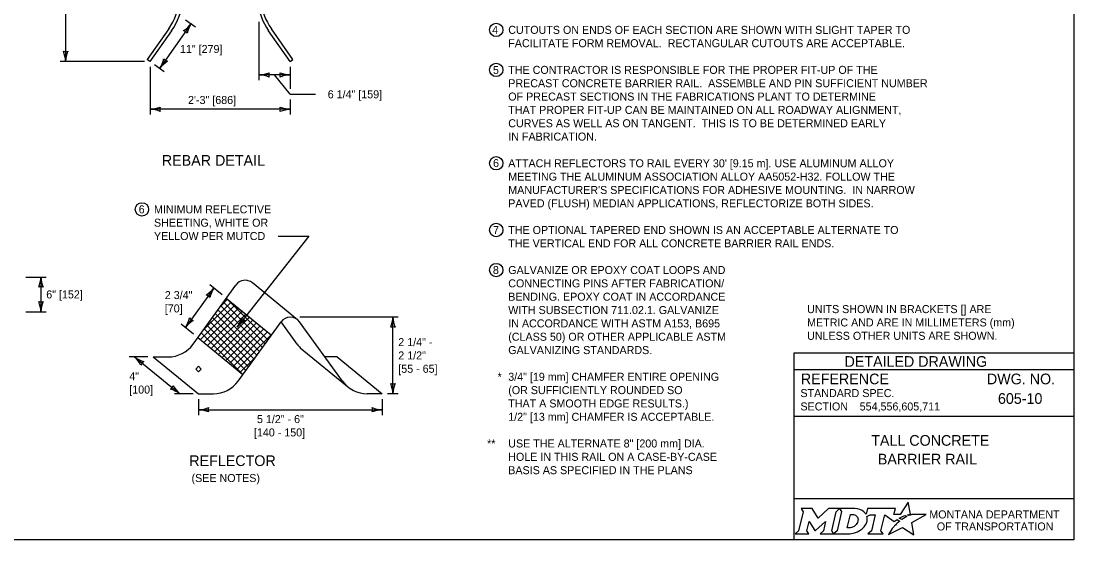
# Model space of a CAD drawing. Extents: x 49991.4 to 50021, y 49987.6 to 50011.4.
# Drawn here: x 50008.86 to 50016.75, y 49987.8 to 49991.69 of the extents above; entities that cross this region are included whole.
import ezdxf

# ---------------------------------------------------------------- set-up
doc = ezdxf.new("R2010")
doc.units = 0
for name, color, linetype in [('Default', 7, 'Continuous'), ('Level 1', 7, 'Continuous'), ('Level 2', 7, 'Continuous'), ('Level 3', 7, 'Continuous'), ('Level 5', 7, 'Continuous')]:
    doc.layers.add(name, color=color, linetype=linetype)

msp = doc.modelspace()

# ---------------------------------------------------------------- linework, layer by layer
at = {"layer": 'Default'}
for points in [[(50015.5126, 49987.9811), (50015.5023, 49987.9867), (50015.5139, 49987.9895), (50015.5255, 49987.9915), (50015.5081, 49988.0816), (50015.4486, 49987.9903), (50015.4013, 49987.9896), (50015.4116, 49988.0337), (50015.2024, 49988.0338), (50015.1923, 49987.9913), (50015.1865, 49987.9996)], [(50014.7056, 49988.0338), (50014.7197, 49988.0104), (50014.6862, 49987.8671), (50014.6605, 49987.8446), (50014.7621, 49987.8446), (50014.7486, 49987.8674), (50014.7648, 49987.9375), (50014.8085, 49987.8685), (50014.8138, 49987.8685), (50014.8889, 49987.938), (50014.8725, 49987.8669), (50014.8478, 49987.8449), (50014.9494, 49987.8449), (50014.9356, 49987.8682), (50014.9688, 49988.0106)], [(50014.9688, 49988.0106), (50014.9941, 49988.0338), (50014.9117, 49988.0338), (50014.8321, 49987.9608), (50014.7876, 49988.0335), (50014.7056, 49988.0338)], [(50015.1077, 49988.0338), (50014.9941, 49988.0338), (50015.0088, 49988.0109), (50014.9749, 49987.8671), (50014.9494, 49987.8449), (50015.06, 49987.8449)], [(50015.1317, 49987.9471), (50015.1305, 49987.939), (50015.1273, 49987.9297), (50015.1231, 49987.9215), (50015.1175, 49987.914), (50015.111, 49987.9071), (50015.1031, 49987.9008), (50015.0948, 49987.8961), (50015.0857, 49987.8922), (50015.0766, 49987.8899), (50015.0674, 49987.889), (50015.0515, 49987.889), (50015.0751, 49987.989), (50015.0911, 49987.989), (50015.0987, 49987.9884), (50015.1063, 49987.9865), (50015.1129, 49987.9835), (50015.119, 49987.9793), (50015.1238, 49987.9743), (50015.1275, 49987.9683), (50015.1302, 49987.9621), (50015.1318, 49987.9547), (50015.1318, 49987.9517), (50015.1317, 49987.9471)], [(50015.1991, 49987.9747), (50015.2237, 49987.9878), (50015.2606, 49987.9878), (50015.232, 49987.8673), (50015.2045, 49987.8446), (50015.3207, 49987.8446), (50015.3037, 49987.8675), (50015.3319, 49987.9877), (50015.4032, 49987.936), (50015.4243, 49987.9511), (50015.444, 49987.9402)], [(50015.3882, 49987.8843), (50015.3729, 49987.8599), (50015.3682, 49987.8524), (50015.3624, 49987.8438), (50015.3601, 49987.8395), (50015.4654, 49987.8926), (50015.5493, 49987.8375), (50015.5362, 49987.9302), (50015.6431, 49987.9886), (50015.5938, 49987.9894), (50015.5637, 49987.9898), (50015.5429, 49987.9901), (50015.5361, 49987.9886), (50015.5312, 49987.9874), (50015.5228, 49987.9851), (50015.5126, 49987.9811)], [(50015.4622, 49987.9535), (50015.4598, 49987.9518), (50015.4415, 49987.9614), (50015.4518, 49987.9671), (50015.4559, 49987.9693), (50015.4645, 49987.9733), (50015.4702, 49987.9759), (50015.4781, 49987.9789), (50015.4854, 49987.9816), (50015.4972, 49987.9742), (50015.4932, 49987.9721), (50015.4886, 49987.9696), (50015.4844, 49987.9674), (50015.4794, 49987.9645), (50015.4775, 49987.9634), (50015.4748, 49987.9618), (50015.4723, 49987.9604), (50015.47, 49987.9588), (50015.4674, 49987.957), (50015.4647, 49987.9552), (50015.4622, 49987.9535)], [(50015.1057, 49987.8522), (50015.1141, 49987.8548), (50015.1271, 49987.8602), (50015.1475, 49987.8712)], [(50015.4021, 49987.9004), (50015.4021, 49987.9004)]]:
    msp.add_lwpolyline(points, dxfattribs=at)
for centre, radius, start, end in [((50015.0868, 49987.9727), 0.1183, 300.91025, 339.13831), ((50015.1308, 49987.9554), 0.0709, 339.53292, 15.85821)]:
    msp.add_arc(centre, radius, start, end, dxfattribs=at)
for centre, major_axis, ratio, start_param, end_param in [((50015.1056, 49987.9864), (0.0834, -0.0037), 0.568097, 0.61298, 1.570796), ((50015.1612, 49987.9937), (0.0361, -0.0295), 0.469099, 1.225588, 1.570796), ((50015.4119, 49987.9106), (-0.0098, -0.0102), 0.016458, 3.141593, 6.279097), ((50015.4329, 49987.9305), (-0.0112, -0.0097), 0.021651, 3.157348, 6.283185), ((50015.0603, 49987.9932), (0, 0.1484), 0.987302, 3.139398, 3.456847), ((50015.3952, 49987.8923), (-0.00694, -0.00806), 0.008222, 0, 3.137361)]:
    msp.add_ellipse(centre, major_axis=major_axis, ratio=ratio, start_param=start_param, end_param=end_param, dxfattribs=at)
at = {"layer": 'Level 1'}
for p, q in [((50009.9662, 49991.6291), (50009.805, 49991.3994)), ((50010.897, 49991.3994), (50010.7358, 49991.6291)), ((50009.9869, 49991.6146), (50009.8257, 49991.385)), ((50010.8763, 49991.385), (50010.7151, 49991.6146)), ((50009.8257, 49991.385), (50009.805, 49991.3994)), ((50010.8763, 49991.385), (50010.897, 49991.3994)), ((50010.1483, 49989.2658), (50010.4691, 49989.7092)), ((50010.9322, 49989.449), (50010.5936, 49989.7253)), ((50010.2237, 49989.37), (50010.4343, 49989.5807)), ((50010.3531, 49989.549), (50010.4071, 49989.6029)), ((50010.3764, 49989.5811), (50010.6888, 49989.2686)), ((50010.3972, 49989.6098), (50010.7096, 49989.2974)), ((50010.3977, 49989.6106), (50010.7364, 49989.3343)), ((50010.2029, 49989.2997), (50010.4616, 49989.5585)), ((50010.2301, 49989.2775), (50010.4889, 49989.5362)), ((50010.2574, 49989.2553), (50010.5161, 49989.514)), ((50010.3348, 49989.5237), (50010.6473, 49989.2112)), ((50010.3556, 49989.5524), (50010.6681, 49989.2399)), ((50010.2725, 49989.4375), (50010.585, 49989.125)), ((50010.2847, 49989.233), (50010.5434, 49989.4918)), ((50010.2933, 49989.4662), (50010.6057, 49989.1538)), ((50010.3119, 49989.2108), (50010.5707, 49989.4695)), ((50010.314, 49989.495), (50010.6265, 49989.1825)), ((50010.3392, 49989.1885), (50010.5979, 49989.4473)), ((50010.3664, 49989.1663), (50010.6252, 49989.425)), ((50010.487, 49988.9896), (50010.8077, 49989.433)), ((50010.9294, 49989.2658), (50010.8081, 49989.4335)), ((50011.2681, 49988.9896), (50010.9473, 49989.433)), ((50010.2102, 49989.3513), (50010.5226, 49989.0389)), ((50010.2309, 49989.3801), (50010.5434, 49989.0676)), ((50010.2517, 49989.4088), (50010.5642, 49989.0963)), ((50010.3937, 49989.1441), (50010.6524, 49989.4028)), ((50010.421, 49989.1218), (50010.6797, 49989.3806)), ((50010.4482, 49989.0996), (50010.707, 49989.3583)), ((50010.184, 49989.3151), (50010.5226, 49989.0389)), ((50010.4755, 49989.0774), (50010.7342, 49989.3361)), ((50010.9518, 49989.2393), (50011.3182, 49988.9391)), ((50009.8499, 49989.1707), (50009.9622, 49989.1707)), ((50009.8499, 49989.1707), (50010.1885, 49988.8945)), ((50010.5027, 49989.0551), (50010.6172, 49989.1695)), ((50011.2278, 49989.1707), (50011.137, 49989.1707)), ((50011.2278, 49989.1707), (50011.5665, 49988.8945)), ((50010.1885, 49988.8945), (50010.3009, 49988.8945)), ((50011.5665, 49988.8945), (50011.4542, 49988.8945))]:
    msp.add_line(p, q, dxfattribs=at)
for points in [[(49999.3835, 49998.9992), (50016.7501, 49998.9992), (50016.7501, 49987.7988), (49999.3835, 49987.7988)], [(50010.1688, 49989.0796), (50010.1895, 49989.059), (50010.2102, 49989.0796), (50010.1895, 49989.1003)]]:
    msp.add_lwpolyline(points, close=True, dxfattribs=at)
for centre, radius, start, end in [((50010.5388, 49989.6588), 0.0861, 50.54606, 144.11896), ((50010.8775, 49989.3825), 0.0861, 35.88104, 144.11896), ((50009.9622, 49989.4004), 0.2297, 270, 324.11897), ((50011.1155, 49989.4004), 0.2297, 215.88103, 224.5527), ((50010.3009, 49989.1242), 0.2297, 270, 324.11897), ((50011.4542, 49989.1242), 0.2297, 215.88103, 270)]:
    msp.add_arc(centre, radius, start, end, dxfattribs=at)
for centre, major_axis, start_param, end_param in [((50009.5873, 49991.8935), (0.4625, 0), 5.672459, 6.178105), ((50009.5873, 49991.8935), (0.4877, 0), 5.672459, 6.178105), ((50011.1146, 49991.8935), (-0.4877, 0), 0.10508, 0.610726), ((50011.1146, 49991.8935), (-0.4625, 0), 0.10508, 0.610726)]:
    msp.add_ellipse(centre, major_axis=major_axis, ratio=0.997211, start_param=start_param, end_param=end_param, dxfattribs=at)
at = {"layer": 'Level 2'}
for centre in [(50012.4207, 49991.6217), (50012.4207, 49991.3217), (50012.4207, 49990.6217), (50009.7657, 49990.2764), (50012.4207, 49990.1217), (50012.4207, 49989.8217)]:
    msp.add_circle(centre, 0.05, dxfattribs=at)
at = {"layer": 'Level 3'}
for p, q in [((50009.1936, 49992.9901), (50009.1936, 49991.385)), ((50010.135, 49991.6684), (50009.8999, 49991.3335)), ((50010.0927, 49991.698), (50010.1678, 49991.6455)), ((50010.6426, 49991.6809), (50010.6426, 49991.244)), ((50009.7857, 49991.385), (50009.1536, 49991.385)), ((50009.8264, 49991.345), (50009.8264, 49990.9862)), ((50009.8587, 49991.3623), (50009.9327, 49991.3106)), ((50010.8764, 49991.345), (50010.8764, 49991.1787)), ((50010.8764, 49991.284), (50010.6426, 49991.284)), ((50010.8764, 49991.1387), (50010.7595, 49991.284)), ((50010.8764, 49991.1387), (50011.0671, 49991.1387)), ((50010.8764, 49991.0987), (50010.8764, 49990.9862)), ((50010.8764, 49991.0262), (50009.8264, 49991.0262)), ((50011.0153, 49990.0765), (50010.4781, 49989.393)), ((50010.7874, 49990.0765), (50011.0153, 49990.0765)), ((50008.8941, 49989.7691), (50009.0484, 49989.7691)), ((50009.0084, 49989.7691), (50009.0084, 49989.5091)), ((50010.3047, 49989.6864), (50010.091, 49989.391)), ((50010.3667, 49989.6359), (50010.2737, 49989.7117)), ((50008.8941, 49989.5091), (50009.0484, 49989.5091)), ((50011.6865, 49989.4686), (50010.9482, 49989.4686)), ((50011.6465, 49988.8945), (50011.6465, 49989.4686)), ((50010.153, 49989.3404), (50010.06, 49989.4163)), ((50009.8099, 49989.1707), (50009.6699, 49989.1707)), ((50009.7099, 49989.1707), (50010.0485, 49988.8945)), ((50010.1485, 49988.8945), (50010.0085, 49988.8945)), ((50011.6865, 49988.8945), (50011.6065, 49988.8945)), ((50010.1885, 49988.8545), (50010.1885, 49988.7345)), ((50011.5665, 49988.8545), (50011.5665, 49988.7345)), ((50010.1885, 49988.7745), (50011.5665, 49988.7745))]:
    msp.add_line(p, q, dxfattribs=at)
for centre, radius, start, end in [((50009.9585, 49991.8035), 0.2223, 302.38878, 322.57229), ((50010.3321, 49991.5441), 0.233, 147.76008, 167.00993), ((50010.0614, 49991.5635), 0.0548, 37.07159, 72.79395), ((50009.1936, 49991.5132), 0.0548, 252.13882, 287.86118), ((50008.9609, 49991.3735), 0.233, 2.82731, 22.07716), ((50009.4157, 49991.3758), 0.2223, 157.45601, 177.63952), ((50009.7029, 49991.4578), 0.233, 327.76008, 347.00993), ((50009.9736, 49991.4384), 0.0548, 217.07159, 252.79395), ((50010.0765, 49991.1984), 0.2223, 122.38878, 142.57229), ((50010.6311, 49991.5167), 0.233, 272.82731, 292.07716), ((50010.6334, 49991.0618), 0.2223, 67.45601, 87.63952), ((50010.7708, 49991.284), 0.0548, 162.13882, 197.86118), ((50010.8856, 49991.5061), 0.2223, 247.45601, 267.63952), ((50010.7482, 49991.284), 0.0548, 342.13882, 17.86118), ((50010.8879, 49991.0513), 0.233, 92.82731, 112.07716), ((50009.8149, 49991.2589), 0.233, 272.82731, 292.07716), ((50009.8172, 49990.8041), 0.2223, 67.45601, 87.63952), ((50009.9546, 49991.0262), 0.0548, 162.13882, 197.86118), ((50010.8856, 49991.2484), 0.2223, 247.45601, 267.63952), ((50010.7482, 49991.0262), 0.0548, 342.13882, 17.86118), ((50010.8879, 49990.7935), 0.233, 92.82731, 112.07716), ((50008.7863, 49989.7783), 0.2223, 337.45601, 357.63952), ((50009.2411, 49989.7806), 0.233, 182.82731, 202.07716), ((50009.0084, 49989.6409), 0.0548, 72.13882, 107.86118), ((50010.1301, 49989.8241), 0.2223, 301.57498, 321.75849), ((50010.5, 49989.5594), 0.233, 146.94628, 166.19613), ((50009.0084, 49989.6373), 0.0548, 252.13882, 287.86118), ((50008.7757, 49989.4976), 0.233, 2.82731, 22.07716), ((50009.2305, 49989.4999), 0.2223, 157.45601, 177.63952), ((50010.2296, 49989.5826), 0.0548, 36.25779, 71.98015), ((50009.8957, 49989.5181), 0.233, 326.94628, 346.19613), ((50010.2656, 49989.2534), 0.2223, 121.57498, 141.75849), ((50010.1661, 49989.4949), 0.0548, 216.25779, 251.98015), ((50010.288, 49989.5278), 0.233, 324.65852, 343.90837), ((50010.6471, 49989.2485), 0.2223, 119.28722, 139.47073), ((50010.5573, 49989.4938), 0.0548, 213.97003, 249.69239), ((50011.4244, 49989.4778), 0.2223, 337.45601, 357.63952), ((50011.8792, 49989.4801), 0.233, 182.82731, 202.07716), ((50011.6465, 49989.3404), 0.0548, 72.13882, 107.86118), ((50009.5624, 49989.0044), 0.2223, 28.25298, 48.43649), ((50009.848, 49989.3583), 0.233, 233.62428, 252.87413), ((50009.8092, 49989.0897), 0.0548, 122.93579, 158.65815), ((50009.9492, 49988.9755), 0.0548, 302.93579, 338.65815), ((50010.196, 49989.0608), 0.2223, 208.25298, 228.43649), ((50011.6465, 49989.0227), 0.0548, 252.13882, 287.86118), ((50011.4138, 49988.883), 0.233, 2.82731, 22.07716), ((50011.8686, 49988.8853), 0.2223, 157.45601, 177.63952), ((50009.9104, 49988.7069), 0.233, 53.62428, 72.87413), ((50010.177, 49989.0072), 0.233, 272.82731, 292.07716), ((50010.3168, 49988.7745), 0.0548, 162.13882, 197.86118), ((50011.5756, 49988.9966), 0.2223, 247.45601, 267.63952), ((50011.4383, 49988.7745), 0.0548, 342.13882, 17.86118), ((50010.1794, 49988.5524), 0.2223, 67.45601, 87.63952), ((50011.578, 49988.5418), 0.233, 92.82731, 112.07716)]:
    msp.add_arc(centre, radius, start, end, dxfattribs=at)
at = {"layer": 'Level 5'}
for p, q in [((50016.7501, 49989.1988), (50014.6501, 49989.1988)), ((50014.6501, 49989.1988), (50014.6501, 49987.7988)), ((50016.7501, 49989.0738), (50014.6501, 49989.0738)), ((50015.1444, 49988.7993), (50015.1444, 49988.7993)), ((50016.3862, 49988.8587), (50016.3862, 49988.8587)), ((50016.7501, 49988.7238), (50014.6501, 49988.7238)), ((50015.7001, 49988.4747), (50015.7001, 49988.4747)), ((50016.7501, 49988.1057), (50014.6501, 49988.1057))]:
    msp.add_line(p, q, dxfattribs=at)

# ---------------------------------------------------------------- texts
at = {"layer": 'Default'}
for s, p in [('MONTANA DEPARTMENT', (50015.6663, 49987.96)), ('OF TRANSPORTATION', (50015.7225, 49987.87))]:
    msp.add_text(s, height=0.06, dxfattribs=at).set_placement(p)
at = {"layer": 'Level 2'}
for s, height, p in [('4', 0.06, (50012.39, 49991.5917)), ('CUTOUTS ON ENDS OF EACH SECTION ARE SHOWN WITH SLIGHT TAPER TO', 0.06, (50012.5107, 49991.5917)), ('FACILITATE FORM REMOVAL.  RECTANGULAR CUTOUTS ARE ACCEPTABLE.', 0.06, (50012.5107, 49991.4917)), ('11" [279]', 0.06, (50010.0502, 49991.448)), ('5', 0.06, (50012.3962, 49991.2906)), ('THE CONTRACTOR IS RESPONSIBLE FOR THE PROPER FIT-UP OF THE ', 0.06, (50012.5107, 49991.2917)), ('PRECAST CONCRETE BARRIER RAIL.  ASSEMBLE AND PIN SUFFICIENT NUMBER ', 0.06, (50012.5107, 49991.1917)), ('6 1/4" [159]', 0.06, (50011.1577, 49991.1087)), ('OF PRECAST SECTIONS IN THE FABRICATIONS PLANT TO DETERMINE ', 0.06, (50012.5107, 49991.0917)), ('2\'-3" [686]', 0.06, (50010.1107, 49991.0662)), ('THAT PROPER FIT-UP CAN BE MAINTAINED ON ALL ROADWAY ALIGNMENT, ', 0.06, (50012.5107, 49990.9917)), ('CURVES AS WELL AS ON TANGENT.  THIS IS TO BE DETERMINED EARLY ', 0.06, (50012.5107, 49990.8917)), ('IN FABRICATION.', 0.06, (50012.5107, 49990.7917)), ('REBAR DETAIL', 0.08, (50009.9147, 49990.6036)), ('6', 0.06, (50012.3966, 49990.5931)), ("ATTACH REFLECTORS TO RAIL EVERY 30' [9.15 m]. USE ALUMINUM ALLOY ", 0.06, (50012.5107, 49990.5917)), ('MEETING THE ALUMINUM ASSOCIATION ALLOY AA5052-H32. FOLLOW THE', 0.06, (50012.5107, 49990.4917)), ("MANUFACTURER'S SPECIFICATIONS FOR ADHESIVE MOUNTING.  IN NARROW", 0.06, (50012.5107, 49990.3917)), ('6', 0.06, (50009.7411, 49990.2464)), ('MINIMUM REFLECTIVE ', 0.06, (50009.8557, 49990.2465)), ('PAVED (FLUSH) MEDIAN APPLICATIONS, REFLECTORIZE BOTH SIDES.', 0.06, (50012.5107, 49990.2917)), ('SHEETING, WHITE OR ', 0.06, (50009.8557, 49990.1465)), ('7', 0.06, (50012.3969, 49990.0917)), ('THE OPTIONAL TAPERED END SHOWN IS AN ACCEPTABLE ALTERNATE TO', 0.06, (50012.5107, 49990.0917)), ('YELLOW PER MUTCD', 0.06, (50009.8557, 49990.0465)), ('THE VERTICAL END FOR ALL CONCRETE BARRIER RAIL ENDS.', 0.06, (50012.5107, 49989.9917)), ('8', 0.06, (50012.3957, 49989.7917)), ('GALVANIZE OR EPOXY COAT LOOPS AND ', 0.06, (50012.5107, 49989.7917)), ('CONNECTING PINS AFTER FABRICATION/', 0.06, (50012.5107, 49989.6917)), ('6" [152]', 0.06, (50009.0484, 49989.6091)), ('2 3/4"', 0.06, (50009.9368, 49989.604)), ('BENDING. EPOXY COAT IN ACCORDANCE ', 0.06, (50012.5107, 49989.5917)), ('[70]', 0.06, (50009.9368, 49989.504)), ('WITH SUBSECTION 711.02.1. GALVANIZE', 0.06, (50012.5107, 49989.4917)), ('UNITS SHOWN IN BRACKETS [] ARE ', 0.06, (50014.7501, 49989.4988)), ('IN ACCORDANCE WITH ASTM A153, B695', 0.06, (50012.5107, 49989.3917)), ('METRIC AND ARE IN MILLIMETERS (mm) ', 0.06, (50014.7501, 49989.3988)), ('(CLASS 50) OR OTHER APPLICABLE ASTM', 0.06, (50012.5107, 49989.2917)), ('UNLESS OTHER UNITS ARE SHOWN.', 0.06, (50014.7501, 49989.2988)), ('2 1/4" - ', 0.06, (50011.6865, 49989.2516)), ('2 1/2"', 0.06, (50011.6865, 49989.1516)), ('GALVANIZING STANDARDS.', 0.06, (50012.5107, 49989.1917)), ('[55 - 65]', 0.06, (50011.6865, 49989.0516)), ('4"', 0.06, (50009.6705, 49988.9958)), ('*', 0.06, (50012.4309, 49988.9917)), ('3/4" [19 mm] CHAMFER ENTIRE OPENING', 0.06, (50012.5107, 49988.9917)), ('[100]', 0.06, (50009.6705, 49988.8958)), ('(OR SUFFICIENTLY ROUNDED SO ', 0.06, (50012.5107, 49988.8917)), ('605-10', 0.08, (50016.1806, 49988.8187)), ('THAT A SMOOTH EDGE RESULTS.)', 0.06, (50012.5107, 49988.7917)), ('554,556,605,711', 0.06, (50015.1444, 49988.7693)), ('5 1/2" - 6"', 0.06, (50010.6276, 49988.6745)), ('1/2" [13 mm] CHAMFER IS ACCEPTABLE.', 0.06, (50012.5107, 49988.6917)), ('[140 - 150]', 0.06, (50010.6048, 49988.5745)), ('**', 0.06, (50012.3521, 49988.4917)), ('USE THE ALTERNATE 8" [200 mm] DIA. ', 0.06, (50012.5107, 49988.4917)), ('TALL CONCRETE', 0.08, (50015.2307, 49988.5047)), ('REFLECTOR', 0.08, (50010.1204, 49988.3528)), ('HOLE IN THIS RAIL ON A CASE-BY-CASE', 0.06, (50012.5107, 49988.3917)), ('BARRIER RAIL', 0.08, (50015.2803, 49988.3647)), ('BASIS AS SPECIFIED IN THE PLANS', 0.06, (50012.5107, 49988.2917)), ('(SEE NOTES)', 0.06, (50010.1372, 49988.2328))]:
    msp.add_text(s, height=height, dxfattribs=at).set_placement(p)
at = {"layer": 'Level 5'}
for s, height, p in [('DETAILED DRAWING', 0.0799, (50015.0311, 49989.0963)), ('REFERENCE', 0.08, (50014.7037, 49988.9654)), ('DWG. NO.', 0.08, (50016.0979, 49988.9654)), ('STANDARD SPEC.', 0.06, (50014.7004, 49988.8694)), ('SECTION', 0.06, (50014.7004, 49988.7694))]:
    msp.add_text(s, height=height, dxfattribs=at).set_placement(p)

doc.saveas('drawing.dxf')
